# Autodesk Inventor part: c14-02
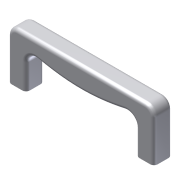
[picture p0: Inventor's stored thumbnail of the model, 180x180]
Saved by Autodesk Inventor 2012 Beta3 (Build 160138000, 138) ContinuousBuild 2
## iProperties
Created: 2011-01
Part Number: c14-02
Material: Default
Document SubType Name: Modeling
Designer: Beta-8540w
Density: 1 g/cm^3
Translation Standard: STEP AP214IS
FileName: C:\Inventor 2012 Essentials\Parts\Chapter 14\c14-01.stp
PreProcessor: Autodesk Inventor 2012
PostProcessor: Build: 138a, Release: 2012 Beta3 - Date: Fri 01/21/2011
Sent Units: millimeter
Uncertainty: 0.01
Author: Beta-8540w
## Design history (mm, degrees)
node "c14-01"
fillet "Fillet1" dims "d0" = 10
fillet "Fillet2" dims "d1" = 4
sketch "Sketch1"
  geometry: L1 (0, 0)-(12, 0) reference; L2 (16, 16)-(16, 4) reference; L3 (140, 0)-(152, 0) reference; 6 further points
  constraints: 3 midpoint, 2 horizontal alignment, 2 vertical alignment
hole "Hole1" sketch "Sketch1" at (6, 10), (146, 10) diameter "d2" = 4.917; stored, may be unused: countersink angle "d6" = 90 deg, drill point angle "d8" = 118 deg; dims "d3" = 12, "d4" = 4, "d5" = 2, "d7" = 14
body "Solid1"
node "Base1"
